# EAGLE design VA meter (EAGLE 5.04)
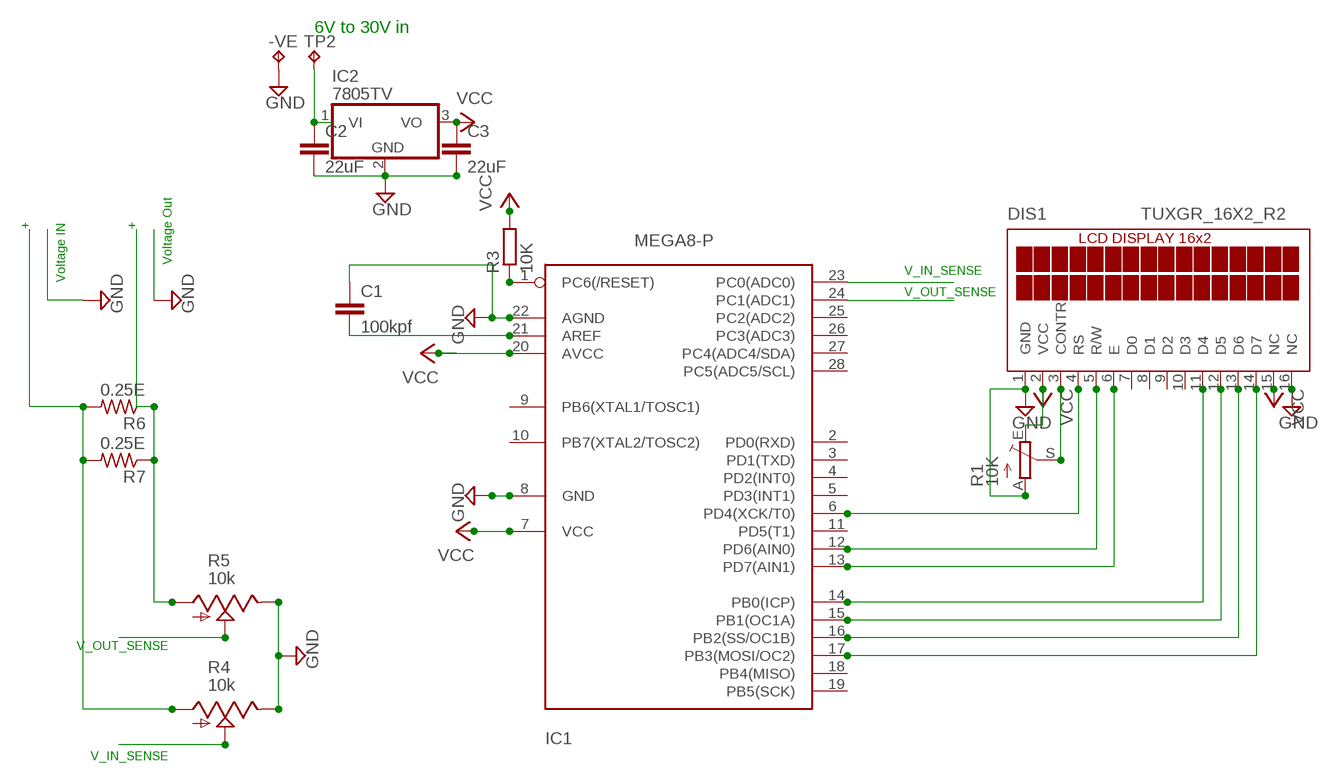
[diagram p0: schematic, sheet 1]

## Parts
-VE  TPPAD1-20Y  [P1-20Y]
C1  100kpf  C5/2.5  [C5B2.5]
C2  22uF  C5/2.5  [C5B2.5]
C3  22uF  C5/2.5  [C5B2.5]
DIS1  TUXGR_16X2_R2  [TUXGR_16X2_R2]
IC1  MEGA8-P  [DIL28-3]
IC2  7805TV  [TO220V]
R1  10K  TRIM_EU-CA9V  [CA9V]
R3  10K  R-EU_0207/10  [0207/10]
R4  10k  TRIM_US-RJ9W  [RJ9W]
R5  10k  TRIM_US-RJ9W  [RJ9W]
R6  0.25E  R-US_0922/22  [0922/22]
R7  0.25E  R-US_0922/22  [0922/22]
TP2  TPPAD1-20Y  [P1-20Y]

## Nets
+VE: C2.1 IC2.1(VI) TP2.1(TP)
GND: -VE.1(TP) C1.1 C2.2 C3.2 DIS1.1(GND) DIS1.16(NC) IC1.8(GND) IC1.22(AGND) IC2.2(GND) R1.A R4.E R5.E
N$1: DIS1.3(CONTR) R1.S
N$3: DIS1.4(RS) IC1.6(PD4(XCK/T0))
N$4: DIS1.5(R/W) IC1.12(PD6(AIN0))
N$5: DIS1.11(D4) IC1.14(PB0(ICP))
N$6: DIS1.12(D5) IC1.15(PB1(OC1A))
N$7: DIS1.13(D6) IC1.16(PB2(SS/OC1B))
N$8: DIS1.14(D7) IC1.17(PB3(MOSI/OC2))
N$9: C1.2 IC1.21(AREF)
N$10: R4.A R6.2 R7.2
N$11: IC1.1(PC6(/RESET)) R3.1
N$12: DIS1.6(E) IC1.13(PD7(AIN1))
N$13: R5.A R6.1 R7.1
V_IN_SENSE: IC1.23(PC0(ADC0)) R4.S
V_OUT_SENSE: IC1.24(PC1(ADC1)) R5.S
VCC: C3.1 DIS1.2(VCC) DIS1.15(NC) IC1.7(VCC) IC1.20(AVCC) IC2.3(VO) R1.E R3.2
Unconnected: DIS1.7(D0) DIS1.8(D1) DIS1.9(D2) DIS1.10(D3) IC1.2(PD0(RXD)) IC1.3(PD1(TXD)) IC1.4(PD2(INT0)) IC1.5(PD3(INT1)) IC1.9(PB6(XTAL1/TOSC1)) IC1.10(PB7(XTAL2/TOSC2)) IC1.11(PD5(T1)) IC1.18(PB4(MISO)) IC1.19(PB5(SCK)) IC1.25(PC2(ADC2)) IC1.26(PC3(ADC3)) IC1.27(PC4(ADC4/SDA)) IC1.28(PC5(ADC5/SCL))

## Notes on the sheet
- 6V to 30V in
- + | +
- Voltage Out
- V_IN_SENSE
- Voltage IN
- V_OUT_SENSE
- V_OUT_SENSE
- V_IN_SENSE

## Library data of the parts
-VE TP2 = testpad:TP: Test pad
C1-C3 = capacitor-wima:C: CAPACITOR
DIS1 = display-lcd:TUXGR_16X2_R2: Tuxgraphics LCD display 16x2 characters reflective, without background light Source: tuxgr_12x2_r2.pdf
IC1 = atmel:MEGA8-P: MICROCONTROLLER 8 Kbytes FLASH, 1 kbytes SRAM, 512 bytes EEPROM, USART, 4-channel 10 bit ADC, 2-channel 8 bit ADC Pin compatible with Atmega48, ATMega88, ATMega168 Source: avr.lbr
IC2 = linear:78*: Positive VOLTAGE REGULATOR Source: http://cache.national.com/ds/LM/LM78L05.pdf http://www.fairchildsemi.com/ds/LM/LM7805.pdf
R1 = pot:TRIM_EU-: POTENTIOMETER
R3 = rcl:R-EU_: RESISTOR, European symbol
R4 R5 = pot:TRIM_US-: POTENTIOMETER
R6 R7 = rcl:R-US_: RESISTOR, American symbol

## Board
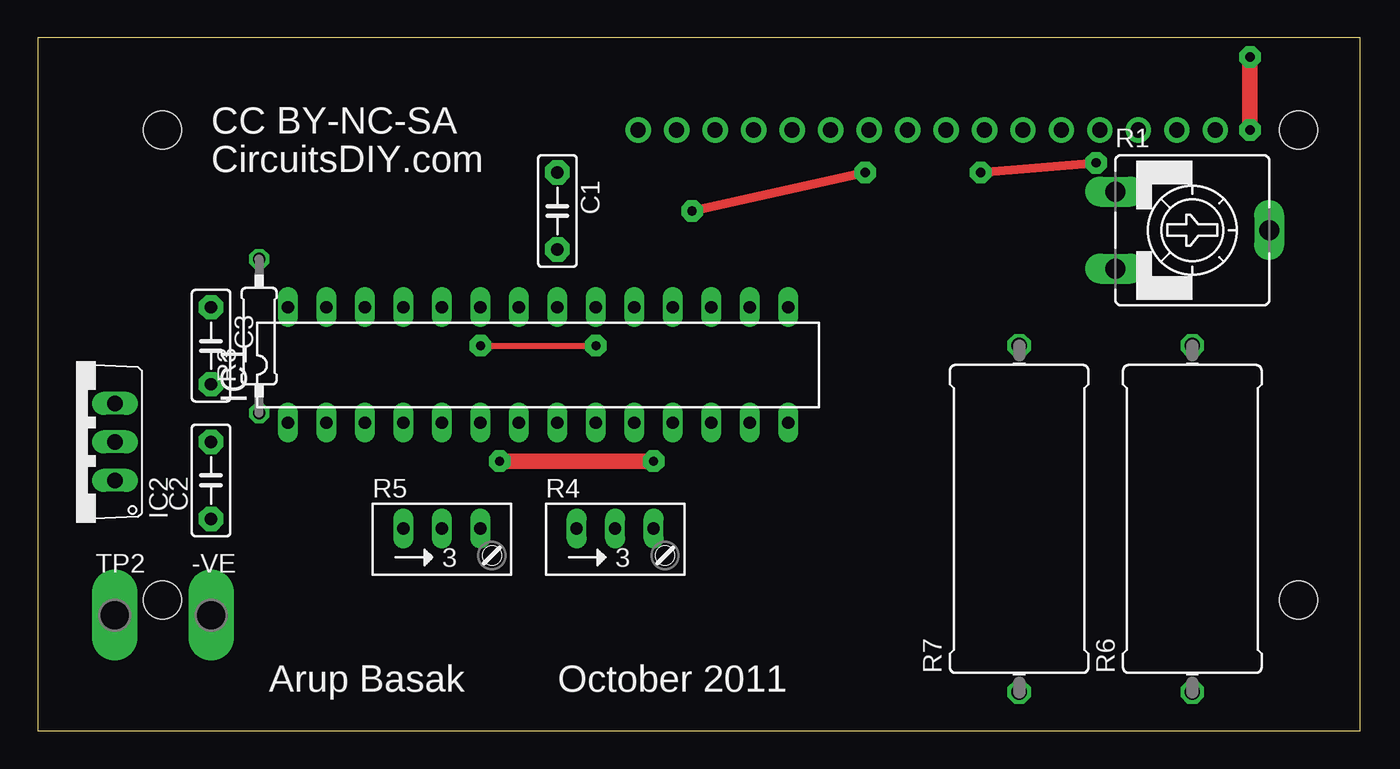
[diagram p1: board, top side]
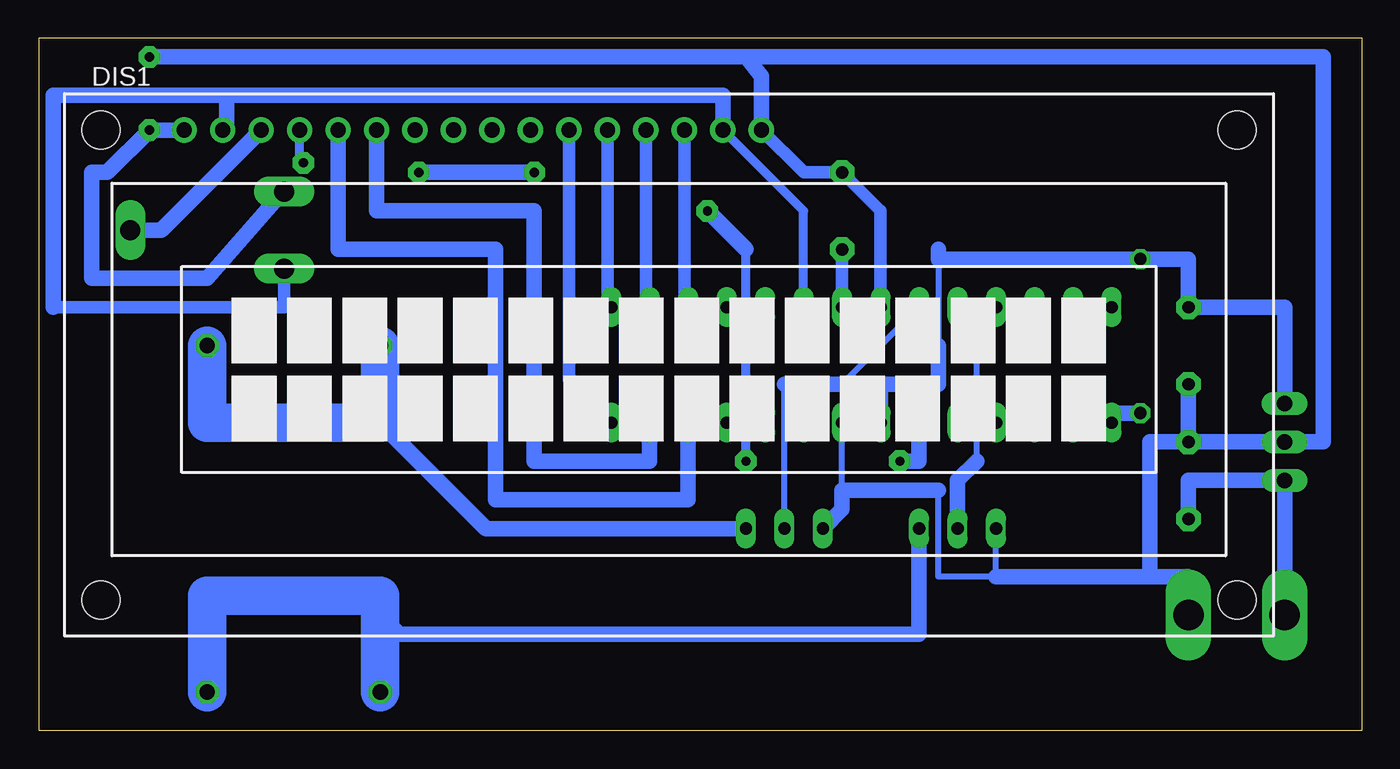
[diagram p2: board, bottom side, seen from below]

Size 87.3 x 45.71 mm. Coordinates in mm from the lower left corner, seen from the top.
Outline: 0,0 87.3,0 87.3,45.71 0,45.71 0,0
Copper layers (1*16): Top 0.035mm / dielectric 1.5mm / Bottom 0.035mm
Design rules "default": minimum track width 10mil, minimum drill 24mil, track to track 16mil, track to pad 16mil, pad to pad 16mil, via to via 16mil, smd to smd 16mil, copper to edge 40mil, drill to drill 50mil, minimum pad ring 10mil, minimum via ring 16mil, stop-mask expansion 4mil, vias tented up to drill 0mil, thermal gap 16mil

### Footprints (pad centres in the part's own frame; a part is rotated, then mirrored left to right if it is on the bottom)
P1-20Y = drill 2.007 pad 2.54 long: 1 0,0
C5B2.5 = drill 0.813 pad 1.6 octagon: 1 -2.54,0; 2 2.54,0
TUXGR_16X2_R2 = drill 1 pad 1.676 round: 1 -32,15.5; 2 -29.46,15.5; 3 -26.92,15.5; 4 -24.38,15.5; 5 -21.84,15.5; 6 -19.3,15.5; 7 -16.76,15.5; 8 -14.22,15.5; 9 -11.68,15.5; 10 -9.14,15.5; 11 -6.6,15.5; 12 -4.06,15.5; 13 -1.52,15.5; 14 1.02,15.5; 15 3.56,15.5; 16 6.1,15.5 | hole 2.5: -37.5,-15.5; 37.5,-15.5; -37.5,15.5; 37.5,15.5
DIL28-3 = drill 0.813 long: 1 -16.51,-3.81; 2 -13.97,-3.81; 3 -11.43,-3.81; 4 -8.89,-3.81; 5 -6.35,-3.81; 6 -3.81,-3.81; 7 -1.27,-3.81; 8 1.27,-3.81; 9 3.81,-3.81; 10 6.35,-3.81; 11 8.89,-3.81; 12 11.43,-3.81; 13 13.97,-3.81; 14 16.51,-3.81; 15 16.51,3.81; 16 13.97,3.81; 17 11.43,3.81; 18 8.89,3.81; 19 6.35,3.81; 20 3.81,3.81; 21 1.27,3.81; 22 -1.27,3.81; 23 -3.81,3.81; 24 -6.35,3.81; 25 -8.89,3.81; 26 -11.43,3.81; 27 -13.97,3.81; 28 -16.51,3.81
TO220V = drill 1.016 long: 1 -2.54,-2.54; 2 0,-2.54; 3 2.54,-2.54
CA9V = drill 1.321 long: A -2.54,-5.08; E 2.54,-5.08; S 0,5.08
0207/10 = drill 0.813 octagon: 1 -5.08,0; 2 5.08,0
RJ9W = drill 0.813 long: A 2.54,0.635; E -2.54,0.635; S 0,0.635
0922/22 = drill 1.016 octagon: 1 -11.43,0; 2 11.43,0

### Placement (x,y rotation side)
-VE  11.43,7.62 0 top
C1  34.29,34.29 270 top
C2  11.43,16.51 90 top
C3  11.43,25.4 270 top
DIS1  45.72,24.13 0 bottom
IC1  33.02,24.13 0 top
IC2  2.54,19.05 90 top
R1  76.2,33.02 270 top
R3  14.61,26.04 90 top
R4  38.1,12.7 0 top
R5  26.67,12.7 0 top
R6  76.2,13.97 90 top
R7  64.77,13.97 90 top
TP2  5.08,7.62 0 top

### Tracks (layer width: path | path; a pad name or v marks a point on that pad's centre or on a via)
+VE
  Bottom 1.016: C2.1 11.43,16.51 IC2.1 TP2.1
GND  (via drill 0.6)
  Top 1.016: v80.01,44.45 v80.01,39.63
  Bottom 0.406: 34.29,15.88 IC1.8 | R5.E 24.13,10.16 27.94,10.16 27.94,15.88
  Bottom 0.813: IC1.22 31.75,34.29 C1.1 36.82,36.83 DIS1.16
  Bottom 1.016: v80.01,39.63 DIS1.1 | DIS1.16 39.62,43.18 40.64,44.45 | R4.E 34.29,14.61 34.29,15.88 27.94,15.88 | -VE.1 11.43,10.16 13.97,10.16 | 13.97,10.16 24.13,10.16 | C2.2 13.97,19.05 13.97,10.16 | C2.2 IC2.2 2.54,19.05 2.54,44.45 40.64,44.45 | C2.2 C3.2 | 40.64,44.45 v80.01,44.45 | v80.01,39.63 80.01,39.37 | v80.01,39.63 82.81,36.83 83.82,36.83 83.82,29.84 76.2,29.84 71.75,34.92 R1.A
N$1
  Bottom 1.016: DIS1.3 79.25,33.02 R1.S
N$3  (via drill 0.6)
  Top 0.61: v43.18,34.29 v54.61,36.83 | v62.23,36.83 v69.85,37.46
  Top 1.016: v30.48,17.78 v40.64,17.78
  Bottom 0.61: v40.64,17.78 40.64,31.75 | v69.85,37.46 70.1,37.71 DIS1.4
  Bottom 1.016: IC1.6 29.21,17.78 v30.48,17.78 | 40.64,31.75 v43.18,34.29 | v54.61,36.83 v62.23,36.83
N$4
  Bottom 1.016: DIS1.5 67.56,31.75 57.15,31.75 57.15,15.24 44.45,15.24 IC1.12
N$5
  Bottom 0.813: DIS1.11 52.32,23.11 IC1.14
N$6
  Bottom 0.813: DIS1.12 49.78,28.19 IC1.15
N$7
  Bottom 0.813: DIS1.13 47.24,28.19 IC1.16
N$8
  Bottom 0.813: DIS1.14 44.7,28.19 IC1.17
N$9
  Bottom 0.813: IC1.21 C1.2
N$10
  Bottom 1.016: R4.A 57.79,13.34 64.77,20.32
  Bottom 2.54: R7.2 64.77,20.32 76.2,20.32 R6.2
N$11
  Bottom 1.016: IC1.1 16.51,20.95 R3.1
N$12
  Bottom 1.016: DIS1.6 65.02,34.29 54.61,34.29 54.61,17.78 46.99,17.78 IC1.13
N$13
  Bottom 1.016: R5.A 29.21,6.35 63.5,6.35 64.77,7.62
  Bottom 2.54: R7.1 64.77,7.62 64.77,8.89 76.2,8.89 R6.1
V_IN_SENSE
  Bottom 0.406: R4.S 38.1,22.86 | 34.29,22.86 IC1.23
  Bottom 1.016: 38.1,22.86 34.29,22.86
V_OUT_SENSE
  Bottom 0.406: 25.4,17.78 25.4,26.67 IC1.24
  Bottom 1.016: R5.S 26.67,16.51 25.4,17.78
VCC  (via drill 0.6)
  Top 0.406: v29.21,25.4 v36.83,25.4
  Bottom 0.406: 27.94,31.75 27.94,25.4 v29.21,25.4 | v36.83,25.4 IC1.20
  Bottom 0.61: IC1.20 36.83,34.3 DIS1.15
  Bottom 0.813: 86.36,27.94 71.12,27.94 R1.E
  Bottom 1.016: IC2.3 5.08,27.94 C3.1 11.43,31.11 R3.2 27.94,31.11 27.94,31.75 | 27.94,25.4 27.94,22.86 31.75,22.86 IC1.7 | DIS1.15 42.16,41.91 74.93,41.91 | DIS1.2 74.93,39.63 74.93,41.91 | 74.93,41.91 86.36,41.91 86.36,27.94

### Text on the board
tNames: CC BY-NC-SA | CircuitsDIY.com | Arup Basak | October 2011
